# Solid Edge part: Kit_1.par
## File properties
Sűrűség: 0,000 kg/m^3
Pontosság: 0,990
Author: ahadarics
Last saved by: psaghy
Revision: 78
Username: ahadarics
Dokumentum tartalom típus: 0
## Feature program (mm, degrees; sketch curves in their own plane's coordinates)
base feature "unnamed BaseFeature 1"
sketch for "Furat_5" plane through (0, 0, 48) normal (0, 0, 1) x-axis (0.707107, -0.707107, 0)
  hole centre (0, 50.9117) bore radius 4.188
hole "Furat_5" nominal diameter 10 finite  VBottomAngle = 118 deg; ThreadDepth = 17 mm
sketch for "unnamed Hole 1" plane through (0, 0, 48) normal (0, 0, 1) x-axis (0.707107, -0.707107, 0)
  hole centre (-50.9117, 0) bore radius 4.188
hole "unnamed Hole 1" finite
sketch for "unnamed Hole 2" plane through (0, 0, 48) normal (0, 0, 1) x-axis (0.707107, -0.707107, 0)
  hole centre (0, -50.9117) bore radius 4.188
hole "unnamed Hole 2" finite
sketch for "unnamed Hole 3" plane through (0, 0, 48) normal (0, 0, 1) x-axis (0.707107, -0.707107, 0)
  hole centre (50.9117, 0) bore radius 4.188
hole "unnamed Hole 3" finite
pattern "unnamed Pattern 1" of "Furat_5", "unnamed Hole 1", "unnamed Hole 2", "unnamed Hole 3"
sketch for "Furat_9" plane through (46.5, -0.0074, 25.7488) normal (1, 0, 0) x-axis (0, 0, 1)
hole "Furat_9" diameter 16.662 finite  ThreadDepth = 17 mm
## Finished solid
Body 1: solid body, 541 faces, 1227 edges, 747 vertices, 7 internal voids.
  Faces by surface: cylinder 200, plane 146, cone 57, sphere 53, torus 47, spline 26, swept 12
  Edges by curve: curve on surface 497, circle 379, line 326, spline 25
Bounding box of the edges (mm; curved faces can reach further): 93.000 x 93.000 x 44.000, from (-46.5, -46.5, 8) to (46.5001, 46.5, 52).
Cylindrical faces by radius (mm): R0.3812 x2, R0.3829 x1, R0.3841 x2, R0.3867 x2, R0.3906 x1, R0.3923 x2, R0.4494 x1, R0.4682 x1, R0.4781 x1, R0.4828 x4, R0.4915 x2, R0.4958 x2, R0.5079 x2, R0.5081 x2, R0.5091 x1, R0.5418 x1, R0.5784 x1, R0.6016 x2, R0.6314 x2, R0.6541 x2, R0.6656 x2, R0.6796 x1, R0.6854 x1, R0.7231 x1, R0.756 x1, R0.7598 x2, R0.7606 x2, R0.7952 x1, R0.7968 x1, R0.8489 x1, R0.8923 x1, R0.9223 x1, R1 x43, R1.0009 x1, R1.0016 x19, R1.0018 x24, R1.01 x1, R1.0286 x1, R1.1393 x1, R1.2532 x1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
Conical faces (half-angle, radius in mm at the cone's reference point): 0.0028 deg R1.0012 x2, 0.0036 deg R1.0008 x6, 1 deg R23.75 x6, 1 deg R35 x6, 30 deg R6.1443 x1, 30 deg R14.8557 x1, 38.6598 deg R31.7888 x6, 38.6598 deg R38.5 x1, 41.1859 deg R39.25 x3, 45 deg R3.75 x1, 45 deg R3.875 x1, 45 deg R5.3 x8, 45 deg R7.85 x8, 45 deg R8.67 x1, 45 deg R12.65 x1, 59 deg R3.25 x1, 59 deg R4.188 x4
Toroidal faces (ring radius, tube radius in mm): R5.3 r0.3 x4, R5.7 r0.3 x1, R7.95 r0.2 x4, R8.65 r0.5 x4, R11.5 r1 x3, R22 r0.5 x1, R23 r0.5 x1, R24.7327 r1 x6, R28.0969 r1 x6, R34.0061 r1 x6, R43 r1 x3, R46.9806 r1 x2, R47 r1 x6
Spherical faces by radius (mm): R1 x53
Planar faces by outward normal: +x 22, +y 8, +z 27, -x 1, -y 8, -z 21, oblique 59
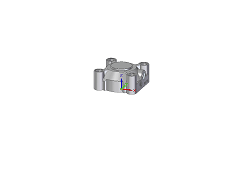
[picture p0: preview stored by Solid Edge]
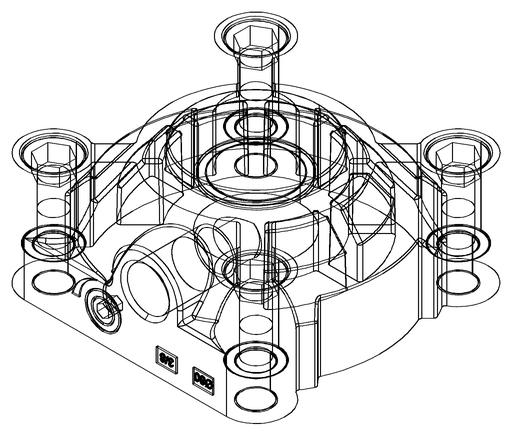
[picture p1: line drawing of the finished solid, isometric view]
